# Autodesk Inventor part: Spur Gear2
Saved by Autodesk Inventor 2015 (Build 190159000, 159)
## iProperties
Created: 2014-06
Part Number: Spur Gear2
Material: Steel
Document SubType Name: Modeling
Designer: User
Categories: <?xml version="1.0" encoding="UTF-16"?> <MemberInstance><Categories><FamilyTemplate><FamilyTemplateParameter ValueType="xs:double" Id="1" ObjectReferenceKey="da
Density: 1 g/cm^3
Appearance: Steel
CustomPartVersion: 1
Author: User
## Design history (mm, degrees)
sketch "Sketch1"
  geometry: C1 r 6.6 at (0, 0)
  constraints: 1 centre point
  dimensions: "d0" = 13.2 diameter of C1 (= da_da)
extrude "Extrusion1" new body sketch "Sketch1" distance "d1" = 6 (= da_b); taper "d2" = 0 deg
workplane "Work Plane2"
sketch "Sketch2"
  geometry: C1 r 6.6 at (0, 0) reference; C2 r 6 at (0, 0)
  constraints: 1 centre point, 1 coincident
  dimensions: "d3" = 12 diameter of C2 (= da_dw)
feature "Pitch Diameter" sketch "Sketch2" dims "d4" = 10, "d5" = 0
workplane "Work Plane8"
workplane "Work Plane9"
feature "Spur Gear" dims "da_b" = 6, "da_d" = 12, "da_aw" = 12, "da_da" = 13.2, "da_df" = 10.5, "da_dw" = 12, angle "da_beta" = 0 deg, "da_lefttooth" = 0, "da_righttooth" = 0
body "Solid1"
body "Srf1"
other parameters: "d16" = 12 (= da_aw), "d17" = 0, "d34" = 9 deg (computed from da_z), "d39" = 0, "d41" = 0, "d43" = 12 (= da_aw), "d46" = 12 (= da_aw), "d47" = 0, "d48" = 0
